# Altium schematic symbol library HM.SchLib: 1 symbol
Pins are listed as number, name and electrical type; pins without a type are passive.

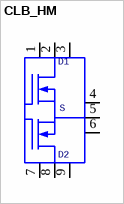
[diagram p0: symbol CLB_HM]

## CLB_HM
designator U?
footprint HM3 (HM3 Module)
pins: 1 V+1, 2 V+2, 3 V+3, 4 MID4, 5 MID5, 6 MID6, 7 V-7, 8 V-8, 9 V-9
